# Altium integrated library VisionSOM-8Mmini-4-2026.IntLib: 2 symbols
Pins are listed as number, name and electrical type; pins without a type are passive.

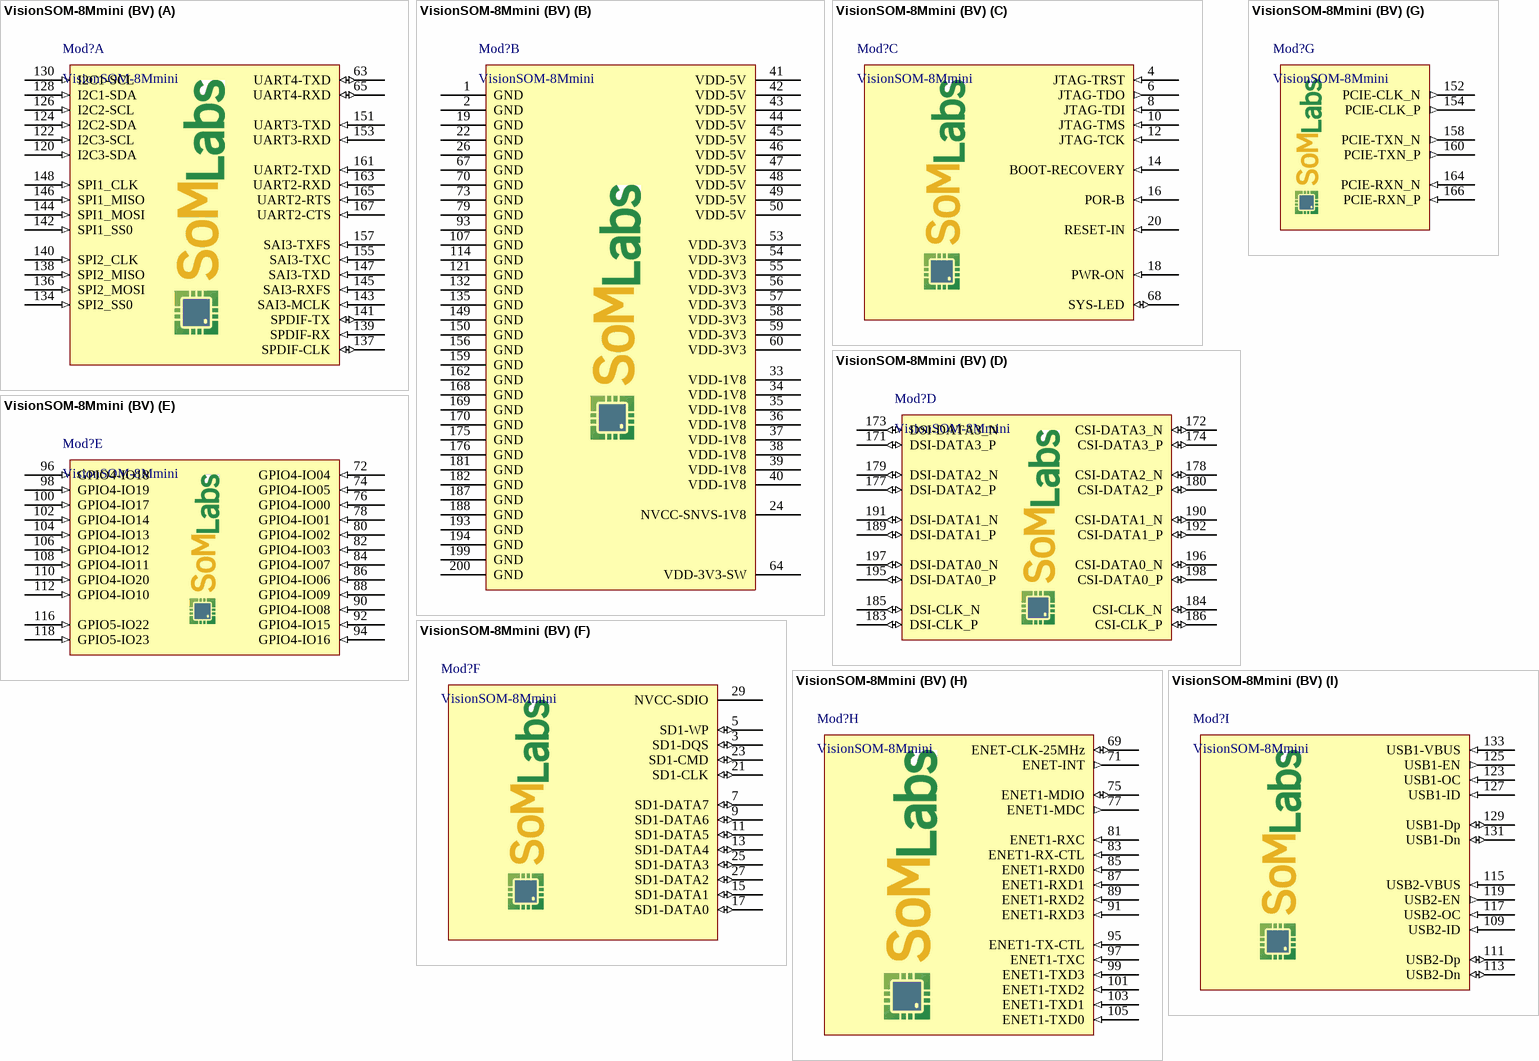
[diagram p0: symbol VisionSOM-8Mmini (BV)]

## VisionSOM-8Mmini (BV)
designator Mod?, comment VisionSOM-8Mmini
Functional blocks view of VisionSOM-8Mmini
footprint J/SODIMM200/TE/1473005-4 (Classic SODIMM200 footprint with SOM mounting hole)
footprint J/SODIMM200/TE/1473005-4+HEATSINK (Classic SODIMM200 footprint with SOM mounting hole and heatsink)
footprint J/SODIMM200/TE/1473005-4+HEATSINK + FAN (Footprint equipped with SOM, hetasink, fan 20x20x10 and mounting holes)
footprint J/SODIMM200/TE/1473005-4+SL-HEATSINK-85x40x10-AB (Footprint equipped with SOM, SL-HEATSINK-85x40x10-Ax hetasink (x=R or W) or SL-HEATSINK-85x40x10-AG heatsink)
part A pins: 63 UART4-TXD (io), 65 UART4-RXD (io), 120 I2C3-SDA (in), 122 I2C3-SCL (in), 124 I2C2-SDA (in), 126 I2C2-SCL (in), 128 I2C1-SDA (in), 130 I2C1-SCL (in), 134 SPI2_SS0 (in), 136 SPI2_MOSI (in), 137 SPDIF-CLK (io), 138 SPI2_MISO (in), 139 SPDIF-RX (in), 140 SPI2_CLK (in), 141 SPDIF-TX (io), 142 SPI1_SS0 (in), 143 SAI3-MCLK (in), 144 SPI1_MOSI (in), 145 SAI3-RXFS (in), 146 SPI1_MISO (in), 147 SAI3-TXD (in), 148 SPI1_CLK (in), 151 UART3-TXD (in), 153 UART3-RXD (in), 155 SAI3-TXC (in), 157 SAI3-TXFS (in), 161 UART2-TXD (in), 163 UART2-RXD (in), 165 UART2-RTS (in), 167 UART2-CTS (in)
part B pins: 1 GND (power), 2 GND (power), 19 GND (power), 22 GND (power), 24 NVCC-SNVS-1V8 (power), 26 GND (power), 33 VDD-1V8 (power), 34 VDD-1V8 (power), 35 VDD-1V8 (power), 36 VDD-1V8 (power), 37 VDD-1V8 (power), 38 VDD-1V8 (power), 39 VDD-1V8 (power), 40 VDD-1V8 (power), 41 VDD-5V (power), 42 VDD-5V (power), 43 VDD-5V (power), 44 VDD-5V (power), 45 VDD-5V (power), 46 VDD-5V (power), 47 VDD-5V (power), 48 VDD-5V (power), 49 VDD-5V (power), 50 VDD-5V (power), 53 VDD-3V3 (power), 54 VDD-3V3 (power), 55 VDD-3V3 (power), 56 VDD-3V3 (power), 57 VDD-3V3 (power), 58 VDD-3V3 (power), 59 VDD-3V3 (power), 60 VDD-3V3 (power), 64 VDD-3V3-SW (power), 67 GND (power), 70 GND (power), 73 GND (power), 79 GND (power), 93 GND (power), 107 GND (power), 114 GND (power), 121 GND (power), 132 GND (power), 135 GND (power), 149 GND (power), 150 GND (power), 156 GND (power), 159 GND (power), 162 GND (power), 168 GND (power), 169 GND (power), 170 GND (power), 175 GND (power), 176 GND (power), 181 GND (power), 182 GND (power), 187 GND (power), 188 GND (power), 193 GND (power), 194 GND (power), 199 GND (power), 200 GND (power)
part C pins: 4 JTAG-TRST (in), 6 JTAG-TDO (out), 8 JTAG-TDI (in), 10 JTAG-TMS (in), 12 JTAG-TCK (in), 14 BOOT-RECOVERY (in), 16 POR-B (in), 18 PWR-ON (in), 20 RESET-IN (in), 68 SYS-LED (io)
part D pins: 171 DSI-DATA3_P (io), 172 CSI-DATA3_N (io), 173 DSI-DATA3_N (io), 174 CSI-DATA3_P (io), 177 DSI-DATA2_P (io), 178 CSI-DATA2_N (io), 179 DSI-DATA2_N (io), 180 CSI-DATA2_P (io), 183 DSI-CLK_P (io), 184 CSI-CLK_N (io), 185 DSI-CLK_N (io), 186 CSI-CLK_P (io), 189 DSI-DATA1_P (io), 190 CSI-DATA1_N (io), 191 DSI-DATA1_N (io), 192 CSI-DATA1_P (io), 195 DSI-DATA0_P (io), 196 CSI-DATA0_N (io), 197 DSI-DATA0_N (io), 198 CSI-DATA0_P (io)
part E pins: 72 GPIO4-IO04 (in), 74 GPIO4-IO05 (in), 76 GPIO4-IO00 (in), 78 GPIO4-IO01 (in), 80 GPIO4-IO02 (in), 82 GPIO4-IO03 (in), 84 GPIO4-IO07 (in), 86 GPIO4-IO06 (in), 88 GPIO4-IO09 (in), 90 GPIO4-IO08 (in), 92 GPIO4-IO15 (in), 94 GPIO4-IO16 (in), 96 GPIO4-IO18 (in), 98 GPIO4-IO19 (in), 100 GPIO4-IO17 (in), 102 GPIO4-IO14 (in), 104 GPIO4-IO13 (in), 106 GPIO4-IO12 (in), 108 GPIO4-IO11 (in), 110 GPIO4-IO20 (in), 112 GPIO4-IO10 (in), 116 GPIO5-IO22 (in), 118 GPIO5-IO23 (in)
part F pins: 3 SD1-DQS (io), 5 SD1-WP (io), 7 SD1-DATA7 (io), 9 SD1-DATA6 (io), 11 SD1-DATA5 (io), 13 SD1-DATA4 (io), 15 SD1-DATA1 (io), 17 SD1-DATA0 (io), 21 SD1-CLK (io), 23 SD1-CMD (io), 25 SD1-DATA3 (io), 27 SD1-DATA2 (io), 29 NVCC-SDIO (power)
part G pins: 152 PCIE-CLK_N (out), 154 PCIE-CLK_P (out), 158 PCIE-TXN_N (out), 160 PCIE-TXN_P (out), 164 PCIE-RXN_N (in), 166 PCIE-RXN_P (in)
part H pins: 69 ENET-CLK-25MHz (io), 71 ENET-INT (out), 75 ENET1-MDIO (io), 77 ENET1-MDC (out), 81 ENET1-RXC (in), 83 ENET1-RX-CTL (in), 85 ENET1-RXD0 (in), 87 ENET1-RXD1 (in), 89 ENET1-RXD2 (in), 91 ENET1-RXD3 (in), 95 ENET1-TX-CTL (in), 97 ENET1-TXC (in), 99 ENET1-TXD3 (in), 101 ENET1-TXD2 (in), 103 ENET1-TXD1 (in), 105 ENET1-TXD0 (in)
part I pins: 109 USB2-ID (in), 111 USB2-Dp (io), 113 USB2-Dn (io), 115 USB2-VBUS (in), 117 USB2-OC (in), 119 USB2-EN (out), 123 USB1-OC (in), 125 USB1-EN (out), 127 USB1-ID (in), 129 USB1-Dp (io), 131 USB1-Dn (io), 133 USB1-VBUS (in)

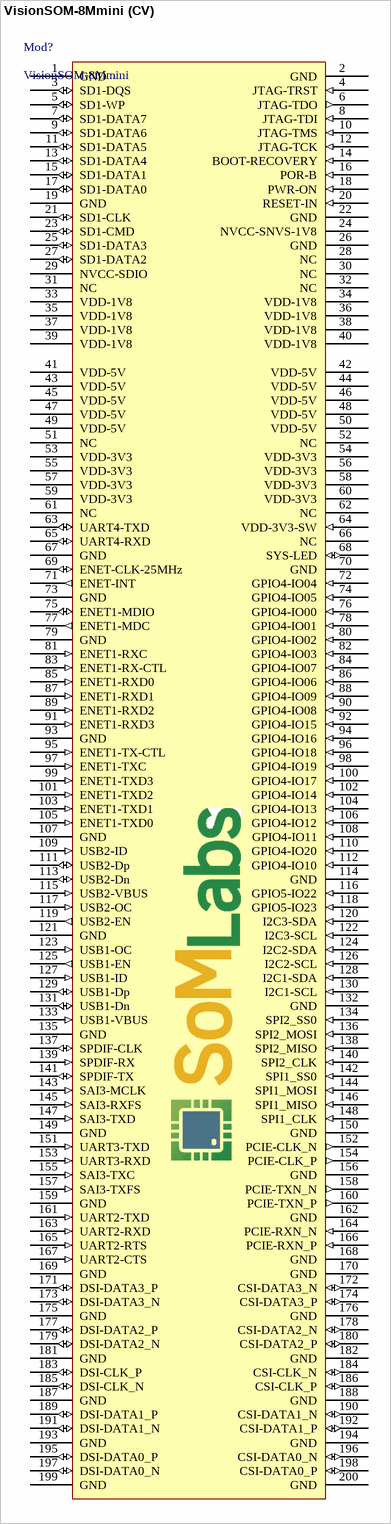
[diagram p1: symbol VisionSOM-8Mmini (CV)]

## VisionSOM-8Mmini (CV)
designator Mod?, comment VisionSOM-8Mmini
Default connector view of VisionSOM-8Mmini
footprint J/SODIMM200/TE/1473005-4+HEATSINK + FAN (Footprint equipped with SOM, hetasink, fan and mounting holes)
footprint J/SODIMM200/TE/1473005-4+HEATSINK (Classic SODIMM200 footprint with SOM mounting hole and heatsink)
footprint J/SODIMM200/TE/1473005-4 (Classic SODIMM200 footprint with SOM mounting hole)
footprint J/SODIMM200/TE/1473005-4+SL-HEATSINK-85x40x10-AB (Footprint equipped with SOM, SL-HEATSINK-85x40x10-Ax hetasink (x=R or W) or SL-HEATSINK-85x40x10-AG heatsink)
pins: 1 GND (power), 2 GND (power), 3 SD1-DQS (io), 4 JTAG-TRST (in), 5 SD1-WP (io), 6 JTAG-TDO (out), 7 SD1-DATA7 (io), 8 JTAG-TDI (in), 9 SD1-DATA6 (io), 10 JTAG-TMS (in), 11 SD1-DATA5 (io), 12 JTAG-TCK (in), 13 SD1-DATA4 (io), 14 BOOT-RECOVERY (in), 15 SD1-DATA1 (io), 16 POR-B (in), 17 SD1-DATA0 (io), 18 PWR-ON (in), 19 GND (power), 20 RESET-IN (in), 21 SD1-CLK (io), 22 GND (power), 23 SD1-CMD (io), 24 NVCC-SNVS-1V8 (power), 25 SD1-DATA3 (io), 26 GND (power), 27 SD1-DATA2 (io), 28 NC, 29 NVCC-SDIO (power), 30 NC, 31 NC, 32 NC, 33 VDD-1V8 (power), 34 VDD-1V8 (power), 35 VDD-1V8 (power), 36 VDD-1V8 (power), 37 VDD-1V8 (power), 38 VDD-1V8 (power), 39 VDD-1V8 (power), 40 VDD-1V8 (power), 41 VDD-5V (power), 42 VDD-5V (power), 43 VDD-5V (power), 44 VDD-5V (power), 45 VDD-5V (power), 46 VDD-5V (power), 47 VDD-5V (power), 48 VDD-5V (power), 49 VDD-5V (power), 50 VDD-5V (power), 51 NC, 52 NC, 53 VDD-3V3 (power), 54 VDD-3V3 (power), 55 VDD-3V3 (power), 56 VDD-3V3 (power), 57 VDD-3V3 (power), 58 VDD-3V3 (power), 59 VDD-3V3 (power), 60 VDD-3V3 (power), 61 NC, 62 NC, 63 UART4-TXD (io), 64 VDD-3V3-SW (in), 65 UART4-RXD (io), 66 NC (power), 67 GND (power), 68 SYS-LED (io), 69 ENET-CLK-25MHz (io), 70 GND (power), 71 ENET-INT (out), 72 GPIO4-IO04 (in), 73 GND (power), 74 GPIO4-IO05 (in), 75 ENET1-MDIO (io), 76 GPIO4-IO00 (in), 77 ENET1-MDC (out), 78 GPIO4-IO01 (in), 79 GND (power), 80 GPIO4-IO02 (in), 81 ENET1-RXC (in), 82 GPIO4-IO03 (in), 83 ENET1-RX-CTL (in), 84 GPIO4-IO07 (in), 85 ENET1-RXD0 (in), 86 GPIO4-IO06 (in), 87 ENET1-RXD1 (in), 88 GPIO4-IO09 (in), 89 ENET1-RXD2 (in), 90 GPIO4-IO08 (in), 91 ENET1-RXD3 (in), 92 GPIO4-IO15 (in), 93 GND (power), 94 GPIO4-IO16 (in), 95 ENET1-TX-CTL (in), 96 GPIO4-IO18 (in), 97 ENET1-TXC (in), 98 GPIO4-IO19 (in), 99 ENET1-TXD3 (in), 100 GPIO4-IO17 (in), 101 ENET1-TXD2 (in), 102 GPIO4-IO14 (in), 103 ENET1-TXD1 (in), 104 GPIO4-IO13 (in), 105 ENET1-TXD0 (in), 106 GPIO4-IO12 (in), 107 GND (power), 108 GPIO4-IO11 (in), 109 USB2-ID (in), 110 GPIO4-IO20 (in), 111 USB2-Dp (io), 112 GPIO4-IO10 (in), 113 USB2-Dn (io), 114 GND (power), 115 USB2-VBUS (in), 116 GPIO5-IO22 (in), 117 USB2-OC (in), 118 GPIO5-IO23 (in), 119 USB2-EN (out), 120 I2C3-SDA (in), 121 GND (power), 122 I2C3-SCL (in), 123 USB1-OC (in), 124 I2C2-SDA (in), 125 USB1-EN (out), 126 I2C2-SCL (in), 127 USB1-ID (in), 128 I2C1-SDA (in), 129 USB1-Dp (io), 130 I2C1-SCL (in), 131 USB1-Dn (io), 132 GND (power), 133 USB1-VBUS (in), 134 SPI2_SS0 (in), 135 GND (power), 136 SPI2_MOSI (in), 137 SPDIF-CLK (io), 138 SPI2_MISO (in), 139 SPDIF-RX (in), 140 SPI2_CLK (in), 141 SPDIF-TX (io), 142 SPI1_SS0 (in), 143 SAI3-MCLK (in), 144 SPI1_MOSI (in), 145 SAI3-RXFS (in), 146 SPI1_MISO (in), 147 SAI3-TXD (in), 148 SPI1_CLK (in), 149 GND (power), 150 GND (power), 151 UART3-TXD (in), 152 PCIE-CLK_N (out), 153 UART3-RXD (in), 154 PCIE-CLK_P (out), 155 SAI3-TXC (in), 156 GND (power), 157 SAI3-TXFS (in), 158 PCIE-TXN_N (out), 159 GND (power), 160 PCIE-TXN_P (out), 161 UART2-TXD (in), 162 GND (power), 163 UART2-RXD (in), 164 PCIE-RXN_N (in), 165 UART2-RTS (in), 166 PCIE-RXN_P (in), 167 UART2-CTS (in), 168 GND (power), 169 GND (power), 170 GND (power), 171 DSI-DATA3_P (io), 172 CSI-DATA3_N (io), 173 DSI-DATA3_N (io), 174 CSI-DATA3_P (io), 175 GND (power), 176 GND (power), 177 DSI-DATA2_P (io), 178 CSI-DATA2_N (io), 179 DSI-DATA2_N (io), 180 CSI-DATA2_P (io), 181 GND (power), 182 GND (power), 183 DSI-CLK_P (io), 184 CSI-CLK_N (io), 185 DSI-CLK_N (io), 186 CSI-CLK_P (io), 187 GND (power), 188 GND (power), 189 DSI-DATA1_P (io), 190 CSI-DATA1_N (io), 191 DSI-DATA1_N (io), 192 CSI-DATA1_P (io), 193 GND (power), 194 GND (power), 195 DSI-DATA0_P (io), 196 CSI-DATA0_N (io), 197 DSI-DATA0_N (io), 198 CSI-DATA0_P (io), 199 GND (power), 200 GND (power)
